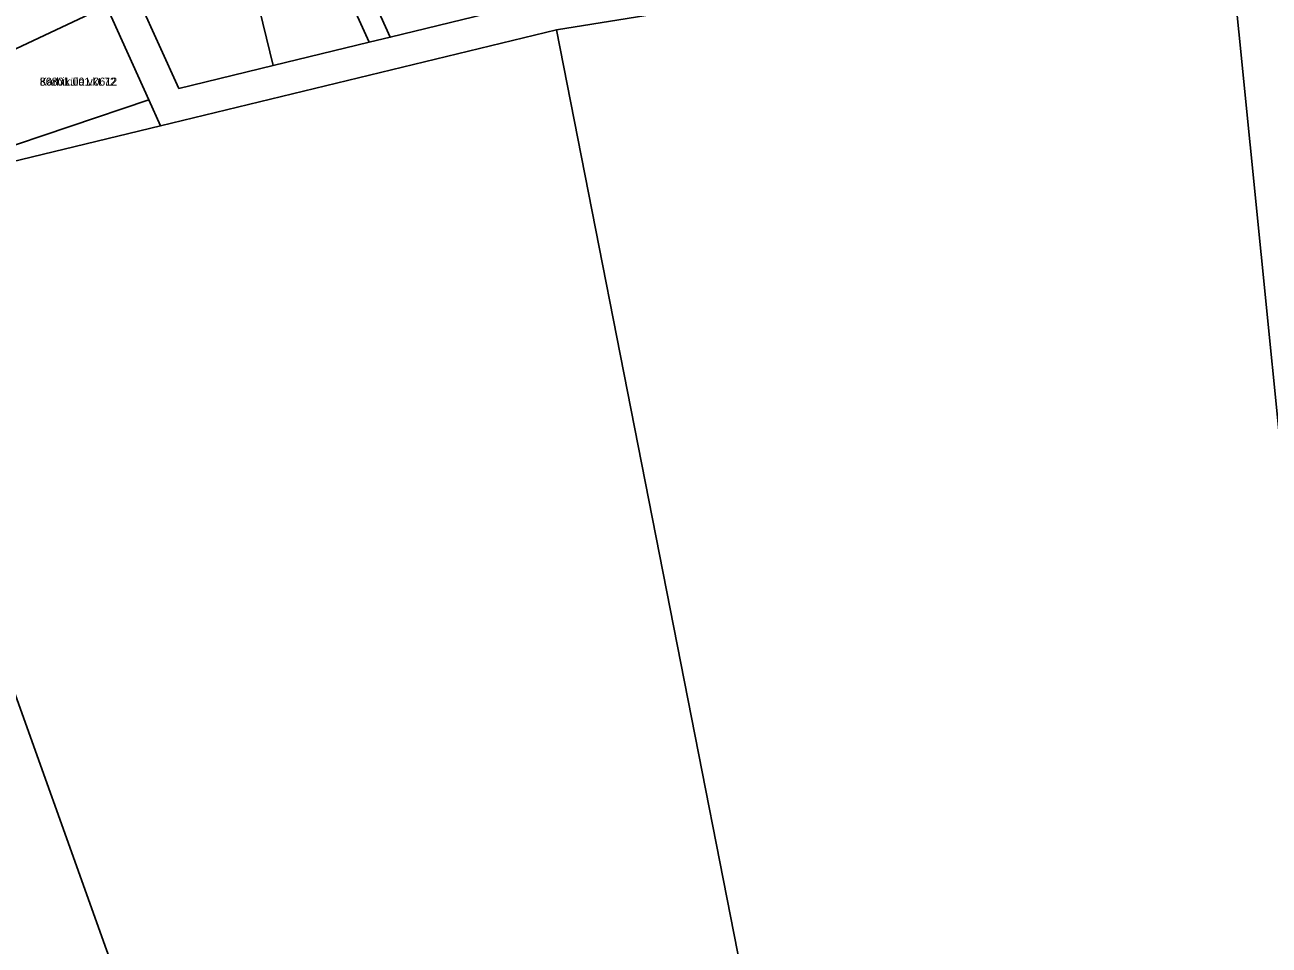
# Model space of a CAD drawing. Extents: x 484607 to 525396, y 6554521 to 6586559.
# Drawn here: x 517147.5 to 517380.7, y 6565115.8 to 6565288.3 of the extents above; entities that cross this region are included whole.
import ezdxf

# ---------------------------------------------------------------- set-up
doc = ezdxf.new("R2010")
doc.units = 0
for name, color, linetype in [('L_AADRESS', 7, 'Continuous'), ('PIIR', 7, 'Continuous'), ('TUNNUS', 7, 'Continuous')]:
    doc.layers.add(name, color=color, linetype=linetype)

msp = doc.modelspace()

# ---------------------------------------------------------------- linework, layer by layer
at = {"layer": 'PIIR'}
for points in [[(517389.61, 6565141.22), (517372.92, 6565307.66), (517371.53, 6565320.36), (517365.62, 6565374.54), (517363.6, 6565393.06), (517361.94, 6565408.22), (517357.88, 6565445.46), (517356.75, 6565455.84), (517355.62, 6565466.19), (517354.54, 6565476.06), (517353.45, 6565486.02), (517352, 6565499.3), (517350.78, 6565510.46), (517349.66, 6565520.75), (517348.53, 6565531.14), (517347.53, 6565540.29), (517346.37, 6565550.88), (517344.46, 6565568.44), (517344.15, 6565574.52), (517326.68, 6565708.93), (517381.83, 6565717.8)], [(517372.92, 6565307.64), (517247.1, 6565287.39), (517172.94, 6565269.42), (517170.74, 6565274.29), (517162.82, 6565291.83)], [(517206.27, 6565307.51), (517215.98, 6565286.02), (517212.02, 6565285.06), (517201.84, 6565307.61)], [(517165.33, 6565300.84), (517176.36, 6565276.42), (517194.02, 6565280.7), (517212.02, 6565285.06), (517215.98, 6565286.02), (517233.94, 6565290.37)], [(517141.07, 6565264.25), (517170.74, 6565274.29), (517172.94, 6565269.42), (517112.75, 6565254.83)], [(516558.37, 6564917.18), (517026.74, 6565221.86), (517112.75, 6565254.83), (517292.22, 6564752.38)]]:
    msp.add_lwpolyline(points, dxfattribs=at)
for points in [[(517206.27, 6565307.51), (517225.22, 6565312.08), (517233.94, 6565290.37), (517215.98, 6565286.02)], [(517116.74, 6565292.98), (517154.68, 6565309.84), (517162.82, 6565291.83), (517125.83, 6565274.49)], [(517165.33, 6565300.84), (517182.8, 6565306.65), (517187.67, 6565306.91), (517194.02, 6565280.7), (517176.36, 6565276.42)], [(517187.67, 6565306.91), (517201.84, 6565307.61), (517212.02, 6565285.06), (517194.02, 6565280.7)], [(517247.1, 6565287.39), (517372.92, 6565307.64), (517389.61, 6565141.2), (517423.81, 6564799.48), (517424.42, 6564793.33), (517424.01, 6564793.33), (517421.1, 6564793.33), (517406.03, 6564790.74), (517391.56, 6564789.69), (517380.65, 6564790.4), (517374.55, 6564790.04), (517369.47, 6564788.41), (517361.44, 6564787.65), (517356.32, 6564787.99), (517348.91, 6564789.36), (517345, 6564788.57), (517343.63, 6564795.47)], [(517125.83, 6565274.49), (517162.82, 6565291.83), (517170.74, 6565274.29), (517141.07, 6565264.25), (517131.98, 6565262.06)], [(517335.42, 6564763.06), (517333.4, 6564759.01), (517329.14, 6564753.22), (517323.96, 6564748.34), (517311.07, 6564747.43), (517304.39, 6564746.53), (517299.38, 6564743.14), (517296.6, 6564740.13), (517292.22, 6564752.38), (517112.75, 6565254.83), (517172.94, 6565269.42), (517247.1, 6565287.39), (517343.63, 6564795.47), (517345, 6564788.57), (517343.38, 6564788.24), (517341.9, 6564785.71), (517340.48, 6564778.56), (517338.13, 6564770.33)]]:
    msp.add_lwpolyline(points, close=True, dxfattribs=at)

# ---------------------------------------------------------------- texts
at = {"layer": 'L_AADRESS'}
msp.add_text('Karbiküla vkt 72', height=1.5, dxfattribs=at).set_placement((517150.3, 6565276.94))
at = {"layer": 'TUNNUS'}
msp.add_text('86801:001:0612', height=1.5, dxfattribs=at).set_placement((517150.3, 6565276.94))

doc.saveas('drawing.dxf')
